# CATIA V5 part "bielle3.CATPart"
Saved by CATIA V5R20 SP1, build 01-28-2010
Part number: bielle3
Bounding box of the stored display mesh (mm): x 9.08 to 113.08, y 0 to 10, z 148.093 to 161.907
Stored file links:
  E:\EDELI\gcausse\Edeli_2012_184_gcausse\bielle3.CATPart
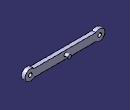
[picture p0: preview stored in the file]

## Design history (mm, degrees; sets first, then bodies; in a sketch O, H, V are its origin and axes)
Body1 (main body)
  Sketch1 on zx-plane, origin (0, 0, 0), H (-1, 0, 0), V (0, 0, 1)
    line L1 (-20.9792, 160) -> (-101.1813, 160)
    line L2 (-20.9792, 150) -> (-101.1813, 150)
    arc A1 centre (-106.0802, 155) radius 7 from (-101.1813, 160) to (-101.1813, 150) ccw
    point P5 (-106.0802, 155)
    arc A2 centre (-16.0802, 155) radius 7 from (-20.9792, 160) to (-20.9792, 150) cw
    point P6 (-16.0802, 155)
    circle A3 centre (-106.0802, 155) radius 2.5
    circle A4 centre (-16.0802, 155) radius 2.5
    radius A2 = 7
    radius A1 = 7
    distance L1 L2 = 10
    distance P6 L1 = 5
    distance P5 L1 = 5
    distance P5 P6 = 90
    radius A3 = 2.5
    radius A4 = 2.5
    horizontal: L1 H, L2 H
  Pad1: profile Sketch1, direction (0, 1, 0), length 5
  Sketch2 on end face of Pad1, origin (0, 5, 0), H (-1, 0, 0), V (0, 0, 1)
    circle A1 centre (-60, 155) radius 2.5
    point P1 (-60, 155)
    reference projected line E1 (-20.9792, 160) -> (-101.1813, 160) from edge [face of Pad1 from Sketch1.L1 | end face of Pad1]
    reference projected line E2 (-101.1813, 150) -> (-20.9792, 150) from edge [face of Pad1 from Sketch1.L2 | end face of Pad1]
    radius A1 = 2.5
    equidistance: E1 E2 P1
  Pad2: profile Sketch2, direction (0, 1, 0), length 5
